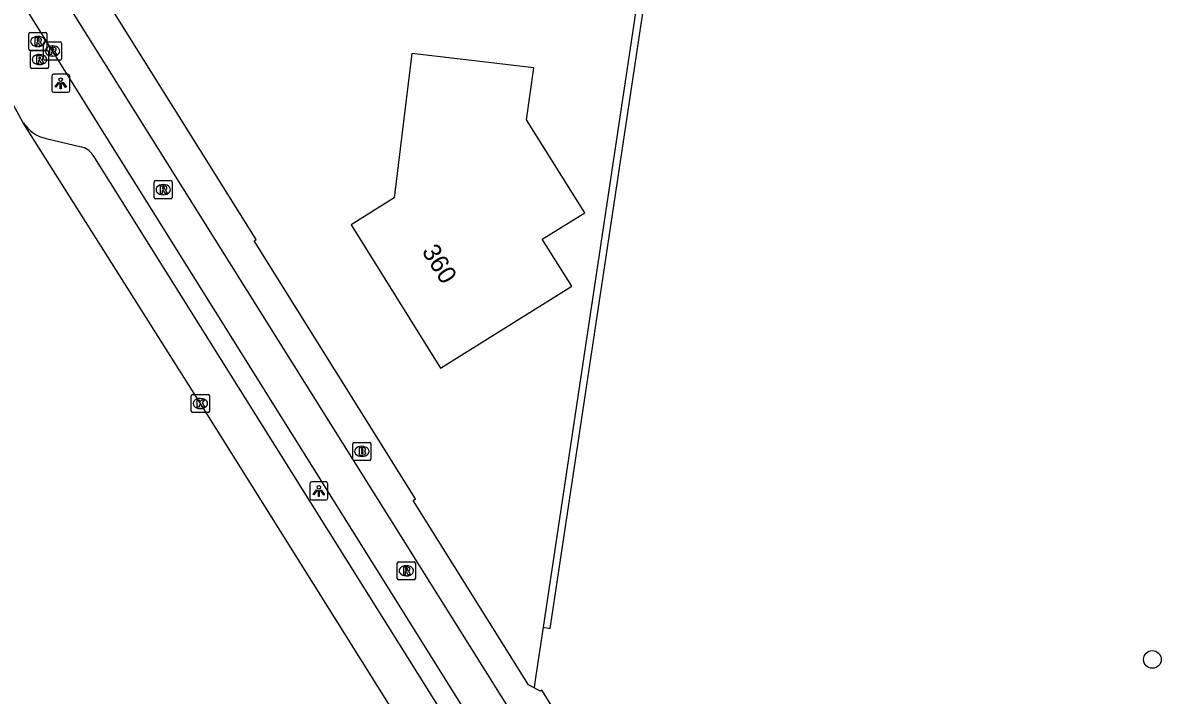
# Model space of a CAD drawing. Extents: x 160026 to 161302, y 384757 to 385701.
# Drawn here: x 160126.7 to 160189.7, y 385117.8 to 385155 of the extents above; entities that cross this region are included whole.
import ezdxf

# ---------------------------------------------------------------- set-up
doc = ezdxf.new("R2010")
doc.units = 0
for name, color, linetype in [('IMGEO_Boom', 7, 'Continuous'), ('IMGEO_Brandkraan', 7, 'Continuous'), ('IMGEO_Fietspad_gesloten', 7, 'Continuous'), ('IMGEO_Grasland_overig', 7, 'Continuous'), ('IMGEO_Haag', 7, 'Continuous'), ('IMGEO_Kolk', 7, 'Continuous'), ('IMGEO_Lichtpunt', 7, 'Continuous'), ('IMGEO_Muur', 7, 'Continuous'), ('IMGEO_Pand', 7, 'Continuous'), ('IMGEO_Pand_nummerreeks', 7, 'Continuous'), ('IMGEO_Parkeervlak_open', 7, 'Continuous'), ('IMGEO_Rijbaan_regionaal_gesloten', 7, 'Continuous'), ('IMGEO_Rioolput', 7, 'Continuous'), ('IMGEO_Voetpad_open', 7, 'Continuous')]:
    doc.layers.add(name, color=color, linetype=linetype)

msp = doc.modelspace()

# ---------------------------------------------------------------- linework, layer by layer
at = {"layer": 'IMGEO_Boom'}
msp.add_circle((160189.208, 385119.806), 0.489, dxfattribs=at)
at = {"layer": 'IMGEO_Brandkraan'}
for p, q in [((160145.055, 385131.809), (160145.907, 385131.809)), ((160144.98, 385130.883), (160144.98, 385131.735)), ((160145.468, 385131.589), (160145.493, 385131.589)), ((160145.981, 385131.735), (160145.981, 385130.883)), ((160145.907, 385130.809), (160145.055, 385130.809)), ((160145.491, 385131.029), (160145.466, 385131.029))]:
    msp.add_line(p, q, dxfattribs=at)
for points in [[(160145.055, 385131.809), (160145.907, 385131.809)], [(160144.98, 385130.883), (160144.98, 385131.735)], [(160145.328, 385131.509), (160145.328, 385131.109), (160145.541, 385131.109)], [(160145.559, 385131.509), (160145.328, 385131.509)], [(160145.507, 385131.428), (160145.453, 385131.428), (160145.453, 385131.352)], [(160145.453, 385131.352), (160145.506, 385131.352)], [(160145.515, 385131.276), (160145.453, 385131.276), (160145.453, 385131.195)], [(160145.453, 385131.195), (160145.515, 385131.195)], [(160145.981, 385131.735), (160145.981, 385130.883)], [(160145.907, 385130.809), (160145.055, 385130.809)]]:
    msp.add_lwpolyline(points, dxfattribs=at)
for centre, radius, start, end in [((160145.057, 385131.733), 0.0765, 91.55205, 178.44795), ((160145.057, 385131.733), 0.0765, 91.55205, 178.44795), ((160145.905, 385131.733), 0.0765, 1.55205, 88.44795), ((160145.905, 385131.733), 0.0765, 1.55205, 88.44795), ((160145.508, 385131.39), 0.0379, 267.82845, 90.93552), ((160145.516, 385131.235), 0.0404, 269.87594, 90.50774), ((160145.563, 385131.364), 0.145, 59.4692, 91.53667), ((160145.588, 385131.411), 0.0922, 285.51372, 58.15012), ((160145.593, 385131.219), 0.105, 301.31148, 78.98903), ((160145.057, 385130.885), 0.0765, 181.55205, 268.44795), ((160145.057, 385130.885), 0.0765, 181.55205, 268.44795), ((160145.547, 385131.36), 0.251, 268.66757, 293.53466), ((160145.905, 385130.885), 0.0765, 271.55205, 358.44795), ((160145.905, 385130.885), 0.0765, 271.55205, 358.44795)]:
    msp.add_arc(centre, radius, start, end, dxfattribs=at)
for centre, major_axis, ratio, start_param, end_param in [((160145.467, 385131.309), (-0.387, 0.002), 0.722429, 4.712389, 7.853982), ((160145.492, 385131.309), (-0.39, 0.002), 0.717154, 1.570796, 4.712389)]:
    msp.add_ellipse(centre, major_axis=major_axis, ratio=ratio, start_param=start_param, end_param=end_param, dxfattribs=at)
at = {"layer": 'IMGEO_Fietspad_gesloten'}
for points in [[(160032.543, 385306.417), (160061.871, 385259.541), (160067.835, 385250), (160085.578, 385221.627), (160124.152, 385160.161), (160150.574, 385117.95), (160168.154, 385089.798)], [(160170.064, 385090.861), (160169.92, 385091.091), (160127.678, 385158.489)]]:
    msp.add_lwpolyline(points, dxfattribs=at)
at = {"layer": 'IMGEO_Grasland_overig'}
msp.add_lwpolyline([(160155.505, 385121.584), (160155.05, 385118.556), (160155.002, 385118.237)], dxfattribs=at)
at = {"layer": 'IMGEO_Haag'}
for points in [[(160163.285, 385173.33), (160162.866, 385170.546), (160155.505, 385121.584)], [(160155.505, 385121.584), (160155.901, 385121.524), (160163.262, 385170.487), (160163.681, 385173.27), (160163.285, 385173.33)]]:
    msp.add_lwpolyline(points, dxfattribs=at)
at = {"layer": 'IMGEO_Kolk'}
for p, q in [((160136.045, 385133.528), (160136.045, 385134.38)), ((160136.12, 385134.454), (160136.972, 385134.454)), ((160137.046, 385134.38), (160137.046, 385133.528)), ((160136.556, 385133.674), (160136.531, 385133.674)), ((160136.533, 385134.234), (160136.558, 385134.234)), ((160136.972, 385133.454), (160136.12, 385133.454))]:
    msp.add_line(p, q, dxfattribs=at)
for points in [[(160136.045, 385133.528), (160136.045, 385134.38)], [(160136.12, 385134.454), (160136.972, 385134.454)], [(160137.046, 385134.38), (160137.046, 385133.528)], [(160136.366, 385134.154), (160136.489, 385134.154), (160136.489, 385134.003), (160136.619, 385134.154), (160136.783, 385134.154), (160136.637, 385134.003), (160136.79, 385133.754), (160136.638, 385133.754), (160136.553, 385133.918), (160136.489, 385133.851), (160136.489, 385133.754), (160136.366, 385133.754), (160136.366, 385134.154)], [(160136.972, 385133.454), (160136.12, 385133.454)]]:
    msp.add_lwpolyline(points, dxfattribs=at)
for centre, start, end in [((160136.122, 385134.378), 91.55205, 178.44795), ((160136.122, 385134.378), 91.55205, 178.44795), ((160136.97, 385134.378), 1.55205, 88.44795), ((160136.97, 385134.378), 1.55205, 88.44795), ((160136.122, 385133.53), 181.55205, 268.44795), ((160136.122, 385133.53), 181.55205, 268.44795), ((160136.97, 385133.53), 271.55205, 358.44795), ((160136.97, 385133.53), 271.55205, 358.44795)]:
    msp.add_arc(centre, 0.0765, start, end, dxfattribs=at)
for centre, major_axis, ratio, start_param, end_param in [((160136.532, 385133.954), (-0.387, 0.002), 0.722429, 4.712389, 7.853982), ((160136.557, 385133.954), (-0.39, 0.002), 0.717154, 1.570796, 4.712389)]:
    msp.add_ellipse(centre, major_axis=major_axis, ratio=ratio, start_param=start_param, end_param=end_param, dxfattribs=at)
at = {"layer": 'IMGEO_Lichtpunt'}
for p, q in [((160128.322, 385152.063), (160128.322, 385151.256)), ((160128.322, 385152.063), (160128.322, 385151.256)), ((160129.224, 385152.158), (160128.416, 385152.158)), ((160129.224, 385152.158), (160128.416, 385152.158)), ((160129.318, 385151.256), (160129.318, 385152.063)), ((160129.318, 385151.256), (160129.318, 385152.063)), ((160128.416, 385151.162), (160129.224, 385151.162)), ((160128.416, 385151.162), (160129.224, 385151.162)), ((160142.599, 385129.524), (160142.599, 385128.717)), ((160142.599, 385129.524), (160142.599, 385128.717)), ((160143.501, 385129.619), (160142.693, 385129.619)), ((160143.501, 385129.619), (160142.693, 385129.619)), ((160143.595, 385128.717), (160143.595, 385129.524)), ((160143.595, 385128.717), (160143.595, 385129.524)), ((160142.693, 385128.623), (160143.501, 385128.623)), ((160142.693, 385128.623), (160143.501, 385128.623))]:
    msp.add_line(p, q, dxfattribs=at)
for points in [[(160128.696, 385151.727), (160128.735, 385151.699), (160128.547, 385151.437), (160128.509, 385151.464), (160128.696, 385151.727)], [(160128.798, 385151.679), (160128.845, 385151.679), (160128.845, 385151.357), (160128.798, 385151.357), (160128.798, 385151.679)], [(160128.908, 385151.699), (160128.946, 385151.726), (160129.133, 385151.464), (160129.094, 385151.436), (160128.908, 385151.699)], [(160142.973, 385129.188), (160143.012, 385129.16), (160142.824, 385128.898), (160142.786, 385128.925), (160142.973, 385129.188)], [(160143.075, 385129.14), (160143.122, 385129.14), (160143.122, 385128.818), (160143.075, 385128.818), (160143.075, 385129.14)], [(160143.185, 385129.16), (160143.223, 385129.187), (160143.41, 385128.925), (160143.371, 385128.897), (160143.185, 385129.16)]]:
    msp.add_lwpolyline(points, dxfattribs=at)
for centre in [(160128.821, 385151.861), (160143.098, 385129.322)]:
    msp.add_circle(centre, 0.0994, dxfattribs=at)
for centre, start, end in [((160128.416, 385152.063), 90, 180), ((160128.416, 385152.063), 90, 180), ((160129.224, 385152.063), 0, 90), ((160129.224, 385152.063), 0, 90), ((160128.416, 385151.256), 180, 270), ((160128.416, 385151.256), 180, 270), ((160129.224, 385151.256), 270, 0), ((160129.224, 385151.256), 270, 360), ((160142.693, 385129.524), 90, 180), ((160142.693, 385129.524), 90, 180), ((160143.501, 385129.524), 0, 90), ((160143.501, 385129.524), 0, 90), ((160142.693, 385128.717), 180, 270), ((160142.693, 385128.717), 180, 270), ((160143.501, 385128.717), 270, 0), ((160143.501, 385128.717), 270, 360)]:
    msp.add_arc(centre, 0.0946, start, end, dxfattribs=at)
at = {"layer": 'IMGEO_Muur'}
msp.add_lwpolyline([(160155.505, 385121.584), (160155.05, 385118.556)], dxfattribs=at)
at = {"layer": 'IMGEO_Pand'}
msp.add_lwpolyline([(160157.086, 385140.44), (160155.462, 385143.037), (160157.809, 385144.504), (160154.594, 385149.645), (160154.983, 385152.521), (160148.247, 385153.311), (160147.264, 385145.32), (160144.881, 385143.83), (160149.835, 385135.907), (160157.086, 385140.44)], dxfattribs=at)
at = {"layer": 'IMGEO_Parkeervlak_open'}
for points in [[(160128.025, 385148.6), (160129.95, 385148.147)], [(160130.602, 385147.694), (160149.652, 385117.292)]]:
    msp.add_lwpolyline(points, dxfattribs=at)
for centre, radius, start, end in [((160128.513, 385150.663), 2.12, 213.81983, 256.68695), ((160129.716, 385147.115), 1.058, 33.18315, 77.23485)]:
    msp.add_arc(centre, radius, start, end, dxfattribs=at)
at = {"layer": 'IMGEO_Rijbaan_regionaal_gesloten'}
for points in [[(160126.752, 385149.483), (160126.191, 385150.495), (160123.75, 385154.328)], [(160149.595, 385113.116), (160147.221, 385116.919), (160136.545, 385133.954), (160126.752, 385149.483)]]:
    msp.add_lwpolyline(points, dxfattribs=at)
at = {"layer": 'IMGEO_Rioolput'}
for p, q in [((160127.131, 385154.472), (160127.983, 385154.472)), ((160127.056, 385153.546), (160127.056, 385154.398)), ((160127.544, 385154.252), (160127.569, 385154.252)), ((160127.868, 385153.019), (160127.868, 385153.871)), ((160127.943, 385153.945), (160128.795, 385153.945)), ((160128.057, 385154.398), (160128.057, 385153.546)), ((160128.869, 385153.871), (160128.869, 385153.019)), ((160127.983, 385153.472), (160127.131, 385153.472)), ((160127.149, 385152.547), (160127.149, 385153.399)), ((160127.224, 385153.473), (160128.076, 385153.473)), ((160127.567, 385153.692), (160127.542, 385153.692)), ((160127.637, 385153.253), (160127.662, 385153.253)), ((160128.15, 385153.399), (160128.15, 385152.547)), ((160128.356, 385153.725), (160128.381, 385153.725)), ((160127.66, 385152.693), (160127.635, 385152.693)), ((160128.795, 385152.945), (160127.943, 385152.945)), ((160128.379, 385153.165), (160128.354, 385153.165)), ((160128.076, 385152.473), (160127.224, 385152.473)), ((160134.068, 385146.278), (160134.92, 385146.278)), ((160133.993, 385145.352), (160133.993, 385146.204)), ((160134.481, 385146.058), (160134.506, 385146.058)), ((160134.994, 385146.204), (160134.994, 385145.352)), ((160134.92, 385145.278), (160134.068, 385145.278)), ((160134.504, 385145.498), (160134.479, 385145.498)), ((160147.438, 385124.282), (160147.438, 385125.134)), ((160147.513, 385125.208), (160148.365, 385125.208)), ((160147.926, 385124.988), (160147.951, 385124.988)), ((160148.439, 385125.134), (160148.439, 385124.282)), ((160147.949, 385124.428), (160147.924, 385124.428)), ((160148.365, 385124.208), (160147.513, 385124.208))]:
    msp.add_line(p, q, dxfattribs=at)
for points in [[(160127.131, 385154.472), (160127.983, 385154.472)], [(160127.056, 385153.546), (160127.056, 385154.398)], [(160127.645, 385154.17), (160127.393, 385154.172), (160127.393, 385153.772)], [(160127.393, 385153.772), (160127.517, 385153.772), (160127.517, 385153.934), (160127.528, 385153.934)], [(160127.571, 385154.091), (160127.517, 385154.091), (160127.517, 385154.01)], [(160127.517, 385154.01), (160127.569, 385154.01)], [(160127.575, 385153.905), (160127.646, 385153.772), (160127.786, 385153.772), (160127.721, 385153.898)], [(160127.868, 385153.019), (160127.868, 385153.871)], [(160127.943, 385153.945), (160128.795, 385153.945)], [(160128.057, 385154.398), (160128.057, 385153.546)], [(160128.869, 385153.871), (160128.869, 385153.019)], [(160127.983, 385153.472), (160127.131, 385153.472)], [(160127.149, 385152.547), (160127.149, 385153.399)], [(160127.224, 385153.473), (160128.076, 385153.473)], [(160128.15, 385153.399), (160128.15, 385152.547)], [(160128.457, 385153.643), (160128.205, 385153.645), (160128.205, 385153.245)], [(160128.205, 385153.245), (160128.329, 385153.245), (160128.329, 385153.407), (160128.34, 385153.407)], [(160128.383, 385153.564), (160128.329, 385153.564), (160128.329, 385153.483)], [(160128.329, 385153.483), (160128.381, 385153.483)], [(160128.387, 385153.378), (160128.458, 385153.245), (160128.598, 385153.245), (160128.533, 385153.371)], [(160127.738, 385153.171), (160127.486, 385153.173), (160127.486, 385152.773)], [(160127.486, 385152.773), (160127.61, 385152.773), (160127.61, 385152.935), (160127.621, 385152.935)], [(160127.664, 385153.092), (160127.61, 385153.092), (160127.61, 385153.011)], [(160127.61, 385153.011), (160127.662, 385153.011)], [(160127.668, 385152.906), (160127.739, 385152.773), (160127.879, 385152.773), (160127.814, 385152.899)], [(160128.795, 385152.945), (160127.943, 385152.945)], [(160128.076, 385152.473), (160127.224, 385152.473)], [(160134.068, 385146.278), (160134.92, 385146.278)], [(160133.993, 385145.352), (160133.993, 385146.204)], [(160134.582, 385145.976), (160134.33, 385145.978), (160134.33, 385145.578)], [(160134.33, 385145.578), (160134.454, 385145.578), (160134.454, 385145.74), (160134.465, 385145.74)], [(160134.508, 385145.897), (160134.454, 385145.897), (160134.454, 385145.816)], [(160134.454, 385145.816), (160134.506, 385145.816)], [(160134.512, 385145.711), (160134.583, 385145.578), (160134.723, 385145.578), (160134.658, 385145.704)], [(160134.994, 385146.204), (160134.994, 385145.352)], [(160134.92, 385145.278), (160134.068, 385145.278)], [(160147.438, 385124.282), (160147.438, 385125.134)], [(160147.513, 385125.208), (160148.365, 385125.208)], [(160148.027, 385124.906), (160147.775, 385124.908), (160147.775, 385124.508)], [(160148.439, 385125.134), (160148.439, 385124.282)], [(160147.775, 385124.508), (160147.899, 385124.508), (160147.899, 385124.67), (160147.91, 385124.67)], [(160147.953, 385124.827), (160147.899, 385124.827), (160147.899, 385124.746)], [(160147.899, 385124.746), (160147.951, 385124.746)], [(160147.957, 385124.641), (160148.028, 385124.508), (160148.168, 385124.508), (160148.103, 385124.634)], [(160148.365, 385124.208), (160147.513, 385124.208)]]:
    msp.add_lwpolyline(points, dxfattribs=at)
for centre, radius, start, end in [((160127.133, 385154.396), 0.0765, 91.55205, 178.44795), ((160127.133, 385154.396), 0.0765, 91.55205, 178.44795), ((160127.981, 385154.396), 0.0765, 1.55205, 88.44795), ((160127.981, 385154.396), 0.0765, 1.55205, 88.44795), ((160127.527, 385153.881), 0.0533, 26.02933, 88.69889), ((160127.553, 385154.199), 0.19, 274.7715, 282.96867), ((160127.577, 385153.995), 0.0964, 77.00612, 93.18647), ((160127.591, 385154.052), 0.0378, 276.66336, 79.67722), ((160127.644, 385154.06), 0.109, 350.36119, 89.41601), ((160127.642, 385154.06), 0.112, 277.58423, 350.98172), ((160127.626, 385153.845), 0.108, 29.51342, 73.79051), ((160127.945, 385153.869), 0.0765, 91.55205, 178.44795), ((160127.945, 385153.869), 0.0765, 91.55205, 178.44795), ((160128.793, 385153.869), 0.0765, 1.55205, 88.44795), ((160128.793, 385153.869), 0.0765, 1.55205, 88.44795), ((160127.133, 385153.548), 0.0765, 181.55205, 268.44795), ((160127.133, 385153.548), 0.0765, 181.55205, 268.44795), ((160127.226, 385153.397), 0.0765, 91.55205, 178.44795), ((160127.226, 385153.397), 0.0765, 91.55205, 178.44795), ((160127.981, 385153.548), 0.0765, 271.55205, 358.44795), ((160127.981, 385153.548), 0.0765, 271.55205, 358.44795), ((160128.074, 385153.397), 0.0765, 1.55205, 88.44795), ((160128.074, 385153.397), 0.0765, 1.55205, 88.44795), ((160128.339, 385153.354), 0.0533, 26.02933, 88.69889), ((160128.365, 385153.672), 0.19, 274.7715, 282.96867), ((160128.389, 385153.468), 0.0964, 77.00612, 93.18647), ((160128.403, 385153.525), 0.0378, 276.66336, 79.67722), ((160128.456, 385153.533), 0.109, 350.36119, 89.41601), ((160128.454, 385153.533), 0.112, 277.58423, 350.98172), ((160128.438, 385153.318), 0.108, 29.51342, 73.79051), ((160127.62, 385152.882), 0.0533, 26.02933, 88.69889), ((160127.646, 385153.2), 0.19, 274.7715, 282.96867), ((160127.67, 385152.996), 0.0964, 77.00612, 93.18647), ((160127.684, 385153.053), 0.0378, 276.66336, 79.67722), ((160127.737, 385153.061), 0.109, 350.36119, 89.41601), ((160127.735, 385153.061), 0.112, 277.58423, 350.98172), ((160127.719, 385152.846), 0.108, 29.51342, 73.79051), ((160127.945, 385153.021), 0.0765, 181.55205, 268.44795), ((160127.945, 385153.021), 0.0765, 181.55205, 268.44795), ((160128.793, 385153.021), 0.0765, 271.55205, 358.44795), ((160128.793, 385153.021), 0.0765, 271.55205, 358.44795), ((160127.226, 385152.549), 0.0765, 181.55205, 268.44795), ((160127.226, 385152.549), 0.0765, 181.55205, 268.44795), ((160128.074, 385152.549), 0.0765, 271.55205, 358.44795), ((160128.074, 385152.549), 0.0765, 271.55205, 358.44795), ((160134.07, 385146.202), 0.0765, 91.55205, 178.44795), ((160134.07, 385146.202), 0.0765, 91.55205, 178.44795), ((160134.918, 385146.202), 0.0765, 1.55205, 88.44795), ((160134.918, 385146.202), 0.0765, 1.55205, 88.44795), ((160134.464, 385145.687), 0.0533, 26.02933, 88.69889), ((160134.49, 385146.005), 0.19, 274.7715, 282.96867), ((160134.514, 385145.801), 0.0964, 77.00612, 93.18647), ((160134.528, 385145.858), 0.0378, 276.66336, 79.67722), ((160134.581, 385145.866), 0.109, 350.36119, 89.41601), ((160134.579, 385145.866), 0.112, 277.58423, 350.98172), ((160134.563, 385145.651), 0.108, 29.51342, 73.79051), ((160134.07, 385145.354), 0.0765, 181.55205, 268.44795), ((160134.07, 385145.354), 0.0765, 181.55205, 268.44795), ((160134.918, 385145.354), 0.0765, 271.55205, 358.44795), ((160134.918, 385145.354), 0.0765, 271.55205, 358.44795), ((160147.515, 385125.132), 0.0765, 91.55205, 178.44795), ((160147.515, 385125.132), 0.0765, 91.55205, 178.44795), ((160148.026, 385124.796), 0.109, 350.36119, 89.41601), ((160148.363, 385125.132), 0.0765, 1.55205, 88.44795), ((160148.363, 385125.132), 0.0765, 1.55205, 88.44795), ((160147.515, 385124.284), 0.0765, 181.55205, 268.44795), ((160147.515, 385124.284), 0.0765, 181.55205, 268.44795), ((160147.909, 385124.617), 0.0533, 26.02933, 88.69889), ((160147.935, 385124.935), 0.19, 274.7715, 282.96867), ((160147.959, 385124.731), 0.0964, 77.00612, 93.18647), ((160147.973, 385124.788), 0.0378, 276.66336, 79.67722), ((160148.024, 385124.796), 0.112, 277.58423, 350.98172), ((160148.008, 385124.581), 0.108, 29.51342, 73.79051), ((160148.363, 385124.284), 0.0765, 271.55205, 358.44795), ((160148.363, 385124.284), 0.0765, 271.55205, 358.44795)]:
    msp.add_arc(centre, radius, start, end, dxfattribs=at)
for centre, major_axis, ratio, start_param, end_param in [((160127.543, 385153.972), (-0.387, 0.002), 0.722429, 4.712389, 7.853982), ((160127.568, 385153.972), (-0.39, 0.002), 0.717154, 1.570796, 4.712389), ((160127.636, 385152.973), (-0.387, 0.002), 0.722429, 4.712389, 7.853982), ((160127.661, 385152.973), (-0.39, 0.002), 0.717154, 1.570796, 4.712389), ((160128.355, 385153.445), (-0.387, 0.002), 0.722429, 4.712389, 7.853982), ((160128.38, 385153.445), (-0.39, 0.002), 0.717154, 1.570796, 4.712389), ((160134.48, 385145.778), (-0.387, 0.002), 0.722429, 4.712389, 7.853982), ((160134.505, 385145.778), (-0.39, 0.002), 0.717154, 1.570796, 4.712389), ((160147.925, 385124.708), (-0.387, 0.002), 0.722429, 4.712389, 7.853982), ((160147.95, 385124.708), (-0.39, 0.002), 0.717154, 1.570796, 4.712389)]:
    msp.add_ellipse(centre, major_axis=major_axis, ratio=ratio, start_param=start_param, end_param=end_param, dxfattribs=at)
at = {"layer": 'IMGEO_Voetpad_open'}
for points in [[(160155.002, 385118.237), (160154.705, 385118.402), (160148.312, 385128.594), (160148.446, 385128.686), (160139.521, 385142.959), (160139.639, 385143.033), (160131.796, 385155.539)], [(160171.885, 385091.874), (160155.435, 385118.099), (160155.339, 385118.049), (160155.002, 385118.237)]]:
    msp.add_lwpolyline(points, dxfattribs=at)

# ---------------------------------------------------------------- texts
at = {"layer": 'IMGEO_Pand_nummerreeks'}
msp.add_text('360', height=1, rotation=302.01643, dxfattribs=at).set_placement((160148.766, 385142.371))

doc.saveas('drawing.dxf')
